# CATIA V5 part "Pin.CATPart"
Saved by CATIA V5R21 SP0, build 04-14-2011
Part number: Pin
Bounding box of the stored display mesh (mm): x -10.997 to 10.997, y 0 to 38, z -10.885 to 10.885
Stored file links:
  D:\CATIA V5R21 E-RESOURCES\CATIA-V5R21\catia-v5r21-Prts\c14_catia_v5r21_prt\c14-catia-v5r21-figr-14-26 & 27\Part & Asm\Pin.CATPart
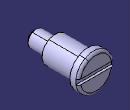
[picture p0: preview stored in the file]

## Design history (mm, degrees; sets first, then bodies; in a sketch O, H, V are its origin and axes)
Body1 (main body)
  Sketch1 on yz-plane, origin (0, 0, 0), H (0, 1, 0), V (0, 0, 1)
    line L1 (0, 0) -> (0, 5)
    line L2 (0, 5) -> (13, 5)
    line L3 (13, 5) -> (13, 8)
    line L4 (13, 8) -> (33, 8)
    line L5 (33, 8) -> (33, 11)
    line L6 (33, 11) -> (38, 11)
    line L7 (38, 11) -> (38, 0)
    point P7 (38, 0)
    line L8 (38, 0) -> (0, 0)
    distance L8 L6 = 11
    distance L4 L8 = 8
    length L8 = 38
    distance L2 L8 = 5
    length L6 = 5
    length L4 = 20
    vertical: L1 V, L3 V, L5 V, L7 V
    horizontal: L2 H, L4 H, L8 H, L6 H
    coincidence: P7 H
  Shaft1: profile Sketch1, axis edge of Sketch1, angle 360
  Chamfer1: length 1.5, angle 45, on 1 edge
  Fillet1: radius 1.5, on 1 edge
  Sketch2 on face of Shaft1, origin (0, 38, 0), H (-1, 0, 0), V (0, 0, 1)
    line L1 (-15.6575, 1.5) -> (20.3727, 1.5)
    line L2 (20.3727, 1.5) -> (20.3727, -1.5)
    line L3 (20.3727, -1.5) -> (-15.6575, -1.5)
    line L4 (-15.6575, -1.5) -> (-15.6575, 1.5)
    distance H L3 = 1.5
    length L4 = 3
    horizontal: L1 H, L3 H
    vertical: L2 V, L4 V
  Pocket1: profile Sketch2, direction (0, -1, 0), length 1.5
